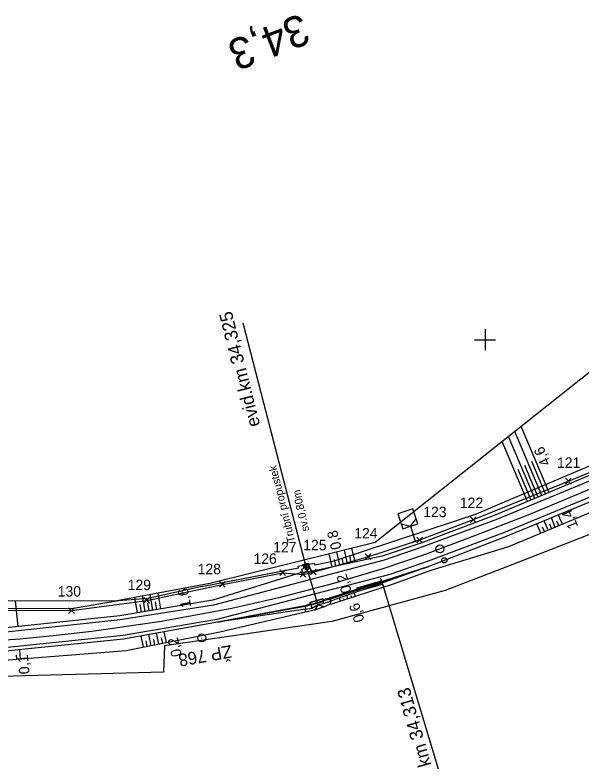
# Model space of a CAD drawing. Extents: x -805730 to -804640, y -1150889 to -1150366.
# Drawn here: x -805190.1 to -805081.4, y -1150682.3 to -1150537.8 of the extents above; entities that cross this region are included whole.
import ezdxf

# ---------------------------------------------------------------- set-up
doc = ezdxf.new("R2010")
doc.units = 0
for name, color, linetype in [('0381KM032-037P - Vrstva 1', 7, 'Continuous'), ('0381KM032-037P - Vrstva 13', 7, 'Continuous'), ('0381KM032-037P - Vrstva 17', 7, 'Continuous'), ('0381KM032-037P - Vrstva 19', 7, 'Continuous'), ('0381KM032-037P - Vrstva 4', 7, 'Continuous'), ('0381KM032-037P - Vrstva 48', 7, 'Continuous'), ('0381KM032-037P - Vrstva 49', 7, 'Continuous'), ('0381KM032-037P - Vrstva 7', 7, 'Continuous'), ('0381KM032-037P - Vrstva 9', 7, 'Continuous'), ('Default', 7, 'Continuous'), ('hran DP - hran DP', 7, 'Continuous'), ('krizky_1000 - Vrstva 1', 7, 'Continuous'), ('PSR_C2_2_Lomove_body_Vimperk - Vrstva 60', 7, 'Continuous'), ('PSR_C2_2_trasa_Vimperk - Kabelová trasa', 7, 'Continuous'), ('vyt_sit - stávající', 7, 'Continuous')]:
    doc.layers.add(name, color=color, linetype=linetype)

msp = doc.modelspace()

# ---------------------------------------------------------------- linework, layer by layer
at = {"layer": '0381KM032-037P - Vrstva 1'}
for points in [[(-805074.24, -1150626.27), (-805091.51, -1150633.48)], [(-805091.51, -1150633.48), (-805101.49, -1150637.38), (-805111.46, -1150641.17)], [(-805111.46, -1150641.17), (-805119.63, -1150643.91), (-805129.05, -1150646.75), (-805139.28, -1150649.43), (-805148.59, -1150651.52), (-805162.04, -1150654.03), (-805175.42, -1150655.94), (-805182.79, -1150656.72)], [(-805182.79, -1150656.72), (-805189.2, -1150657.4), (-805199.42, -1150658.12), (-805222.35, -1150659), (-805235.71, -1150659.34), (-805248.65, -1150659.92), (-805262.34, -1150660.99)]]:
    msp.add_lwpolyline(points, dxfattribs=at)
at = {"layer": '0381KM032-037P - Vrstva 13'}
for p, q in [((-805129.78, -1150649.7), (-805129.65, -1150650.12)), ((-805133.42, -1150650.74), (-805132.59, -1150650.52)), ((-805133.42, -1150650.74), (-805133.23, -1150651.44)), ((-805131.99, -1150650.77), (-805132.69, -1150651.85)), ((-805131.99, -1150650.77), (-805132.2, -1150650.41)), ((-805131.99, -1150650.77), (-805130.88, -1150651.21)), ((-805131, -1150650.07), (-805131.81, -1150650.3)), ((-805130.99, -1150650.58), (-805131, -1150650.07))]:
    msp.add_line(p, q, dxfattribs=at)
for points in [[(-805129.89, -1150649.51), (-805129.78, -1150649.7), (-805131, -1150650.07), (-805131, -1150650.07), (-805131.07, -1150649.74), (-805129.89, -1150649.51)], [(-805134.49, -1150651.14), (-805134.56, -1150650.98), (-805133.46, -1150650.58), (-805133.42, -1150650.74), (-805133.42, -1150650.74), (-805134.49, -1150651.14), (-805134.45, -1150651.61)], [(-805129.65, -1150650.12), (-805129.71, -1150650.67), (-805130.88, -1150651.21), (-805132.69, -1150651.85), (-805134.43, -1150652.2), (-805134.45, -1150651.61), (-805133.23, -1150651.44)], [(-805133.23, -1150651.44), (-805131.99, -1150650.77), (-805130.99, -1150650.58)], [(-805130.99, -1150650.58), (-805129.65, -1150650.12)]]:
    msp.add_lwpolyline(points, dxfattribs=at)
msp.add_ellipse((-805132.2, -1150650.41), major_axis=(-0.388, -0.106), ratio=0.004829, start_param=3.14712, end_param=6.275171, dxfattribs=at)
at = {"layer": '0381KM032-037P - Vrstva 17'}
msp.add_lwpolyline([(-805070.8, -1150598.9), (-805121.06, -1150638.84), (-805152.76, -1150646.7), (-805170.92, -1150650.08), (-805194.39, -1150650.05), (-805213.2, -1150651.26), (-805221.79, -1150652.33), (-805228.79, -1150654.03)], dxfattribs=at)
at = {"layer": '0381KM032-037P - Vrstva 19'}
for p, q in [((-805146.46, -1150596.75), (-805134.12, -1150644.47)), ((-805133.42, -1150650.74), (-805132.59, -1150650.52)), ((-805133.42, -1150650.74), (-805133.42, -1150650.74)), ((-805133.38, -1150650.83), (-805130.98, -1150650.17)), ((-805133.38, -1150650.83), (-805130.98, -1150650.17)), ((-805131.81, -1150650.3), (-805131, -1150650.07))]:
    msp.add_line(p, q, dxfattribs=at)
for points in [[(-805134.98, -1150644.55), (-805135.16, -1150643.96), (-805134.72, -1150643.76), (-805134.94, -1150643.05), (-805134.71, -1150643.05), (-805134.48, -1150643.83)], [(-805134.98, -1150644.55), (-805133.26, -1150644.39), (-805133.87, -1150642.97), (-805134.1, -1150642.94), (-805133.82, -1150643.72)], [(-805134.1, -1150642.94), (-805134.37, -1150642.96), (-805134.71, -1150643.05)], [(-805134.37, -1150642.96), (-805134.35, -1150643.15), (-805134.27, -1150643.62), (-805132.2, -1150650.41)], [(-805133.52, -1150650.35), (-805133.38, -1150650.83), (-805133.38, -1150650.83), (-805133.42, -1150650.74), (-805131, -1150650.07), (-805130.98, -1150650.17), (-805130.98, -1150650.17), (-805131.11, -1150649.68), (-805133.52, -1150650.35)], [(-805131.11, -1150649.68), (-805131.11, -1150649.68), (-805131.07, -1150649.74), (-805131, -1150650.07), (-805131, -1150650.07)], [(-805133.52, -1150650.35), (-805133.52, -1150650.35), (-805133.46, -1150650.58), (-805133.42, -1150650.74)]]:
    msp.add_lwpolyline(points, dxfattribs=at)
for centre, major_axis, ratio, start_param, end_param in [((-805134.15, -1150643.86), (0.331, 0.133), 0.755735, 2.535553, 6.304808), ((-805134.15, -1150643.86), (0.331, 0.133), 0.755735, 0.021623, 2.535553), ((-805132.2, -1150650.41), (0.388, 0.106), 0.004829, 1.569477, 6.288713), ((-805132.2, -1150650.41), (-0.388, -0.106), 0.004829, 3.14712, 4.71107)]:
    msp.add_ellipse(centre, major_axis=major_axis, ratio=ratio, start_param=start_param, end_param=end_param, dxfattribs=at)
at = {"layer": '0381KM032-037P - Vrstva 4'}
for points in [[(-804872.17, -1150539.66), (-804893.72, -1150547.52), (-804911.96, -1150555), (-804952.93, -1150572.63), (-804995.29, -1150590.69), (-805039.86, -1150609.18), (-805057.83, -1150616.69), (-805068.36, -1150621.07), (-805097.92, -1150633.57)], [(-804864.42, -1150538.53), (-804893.06, -1150548.77), (-804911.6, -1150556.2), (-804952.82, -1150573.68), (-804994.86, -1150591.44), (-805039.39, -1150610.13), (-805056.71, -1150617.44), (-805097.6, -1150634.39)], [(-804862.73, -1150542.41), (-804863.39, -1150541.46), (-804892.29, -1150551.48), (-804910.22, -1150558.86), (-804951.61, -1150576.23), (-804993.7, -1150593.96), (-805038.63, -1150612.92), (-805049.62, -1150617.53), (-805055.59, -1150619.94), (-805066.74, -1150624.75), (-805096.44, -1150637.01)], [(-804864.94, -1150543.15), (-804869.59, -1150544.8), (-804891.93, -1150552.26), (-804909.8, -1150559.87), (-804951.24, -1150577.2), (-804993.38, -1150594.6), (-805038.39, -1150613.8), (-805059.54, -1150622.79), (-805066.49, -1150625.57), (-805096.25, -1150637.87)], [(-805097.92, -1150633.57), (-805112.32, -1150638.96), (-805119.74, -1150641.46), (-805133.26, -1150644.39)], [(-805097.6, -1150634.39), (-805112.1, -1150639.75), (-805119.36, -1150642.27), (-805152.08, -1150650.89), (-805169.94, -1150653.7), (-805193.71, -1150656.24), (-805212.28, -1150657.22)], [(-805096.44, -1150637.01), (-805110.9, -1150642.46), (-805118.26, -1150644.98), (-805151.42, -1150653.61), (-805169.41, -1150656.67), (-805193.4, -1150659.17), (-805212.01, -1150660.08)], [(-805096.25, -1150637.87), (-805110.77, -1150643.45), (-805117.97, -1150645.76), (-805129.89, -1150649.51)], [(-805134.98, -1150644.55), (-805152.23, -1150649.93), (-805170.06, -1150652.94), (-805193.76, -1150655.4), (-805212.2, -1150656.84), (-805228.99, -1150656.61)], [(-805134.56, -1150650.98), (-805151.31, -1150654.12), (-805169.36, -1150657.36), (-805193.31, -1150659.84), (-805211.96, -1150660.88), (-805220.23, -1150661.07)]]:
    msp.add_lwpolyline(points, dxfattribs=at)
at = {"layer": '0381KM032-037P - Vrstva 48'}
for p, q in [((-805089.11, -1150629.85), (-805094.3, -1150617.57)), ((-805087.73, -1150629.26), (-805093.08, -1150616.6)), ((-805090.49, -1150630.43), (-805095.52, -1150618.54)), ((-805091.87, -1150631.02), (-805096.74, -1150619.51)), ((-805088.42, -1150629.55), (-805091.05, -1150623.32)), ((-805091.18, -1150630.72), (-805093.66, -1150624.87)), ((-805089.8, -1150630.14), (-805092.35, -1150624.1)), ((-805085.16, -1150635.34), (-805085.89, -1150633.59)), ((-805087.93, -1150636.49), (-805088.67, -1150634.73)), ((-805086.55, -1150635.91), (-805087.28, -1150634.16)), ((-805085.85, -1150635.62), (-805086.22, -1150634.75)), ((-805089.32, -1150637.07), (-805090.05, -1150635.3)), ((-805088.62, -1150636.78), (-805088.99, -1150635.9)), ((-805087.24, -1150636.2), (-805087.61, -1150635.32)), ((-805129.34, -1150643.54), (-805129.89, -1150641.03)), ((-805127.87, -1150643.22), (-805128.43, -1150640.67)), ((-805126.41, -1150642.91), (-805126.97, -1150640.3)), ((-805124.94, -1150642.59), (-805125.52, -1150639.94)), ((-805128.61, -1150643.38), (-805128.88, -1150642.11)), ((-805127.14, -1150643.06), (-805127.42, -1150641.78)), ((-805125.68, -1150642.75), (-805125.96, -1150641.44)), ((-805125.89, -1150648.25), (-805125.84, -1150648.39)), ((-805166.64, -1150652.36), (-805167.14, -1150649.38)), ((-805165.16, -1150652.11), (-805165.66, -1150649.1)), ((-805163.68, -1150651.86), (-805164.19, -1150648.83)), ((-805162.2, -1150651.61), (-805162.71, -1150648.55)), ((-805128.75, -1150649.15), (-805128.69, -1150649.34)), ((-805128.03, -1150648.93), (-805128.01, -1150649.01)), ((-805127.72, -1150650.11), (-805127.92, -1150649.5)), ((-805127.32, -1150648.7), (-805127.27, -1150648.86)), ((-805127.01, -1150649.88), (-805127.11, -1150649.57)), ((-805126.6, -1150648.48), (-805126.58, -1150648.55)), ((-805126.29, -1150649.66), (-805126.5, -1150649)), ((-805125.58, -1150649.43), (-805125.69, -1150649.09)), ((-805124.86, -1150649.2), (-805125.09, -1150648.51)), ((-805189.5, -1150654.96), (-805190.01, -1150650.05)), ((-805165.9, -1150652.24), (-805166.15, -1150650.74)), ((-805164.42, -1150651.99), (-805164.67, -1150650.48)), ((-805162.94, -1150651.74), (-805163.19, -1150650.22)), ((-805165.5, -1150658.95), (-805165.94, -1150656.75)), ((-805164.03, -1150658.66), (-805164.46, -1150656.48)), ((-805162.56, -1150658.36), (-805162.99, -1150656.22)), ((-805161.09, -1150658.07), (-805161.51, -1150655.95)), ((-805164.77, -1150658.8), (-805164.98, -1150657.71)), ((-805163.3, -1150658.51), (-805163.51, -1150657.43)), ((-805161.82, -1150658.22), (-805162.04, -1150657.15)), ((-805189.06, -1150661.23), (-805189.2, -1150659.41)), ((-805189.8, -1150661.29), (-805189.88, -1150660.39))]:
    msp.add_line(p, q, dxfattribs=at)
at = {"layer": '0381KM032-037P - Vrstva 49'}
for p, q in [((-805134.98, -1150644.55), (-805133.26, -1150644.39)), ((-805129.78, -1150649.7), (-805117.97, -1150645.76)), ((-805134.49, -1150651.14), (-805151.31, -1150654.12)), ((-805134.45, -1150651.61), (-805151.31, -1150654.12))]:
    msp.add_line(p, q, dxfattribs=at)
for points in [[(-804871.36, -1150538.86), (-804872.17, -1150539.66), (-804893.72, -1150547.52), (-804911.96, -1150555), (-804952.93, -1150572.63), (-804995.29, -1150590.69), (-805039.86, -1150609.18), (-805057.83, -1150616.69), (-805068.36, -1150621.07), (-805097.92, -1150633.57)], [(-804909.8, -1150559.87), (-804951.24, -1150577.2), (-804993.38, -1150594.6), (-805038.39, -1150613.8), (-805050.01, -1150619.25), (-805055.21, -1150621.51), (-805059.54, -1150622.79), (-805066.49, -1150625.57), (-805096.25, -1150637.87)], [(-805070.8, -1150598.9), (-805121.06, -1150638.84), (-805152.76, -1150646.7), (-805170.92, -1150650.08), (-805194.39, -1150650.05), (-805213.2, -1150651.26), (-805221.79, -1150652.33), (-805228.79, -1150654.03)], [(-805065.73, -1150627.22), (-805095.53, -1150639.67)], [(-805097.92, -1150633.57), (-805112.32, -1150638.96), (-805119.74, -1150641.46), (-805133.26, -1150644.39)], [(-805096.25, -1150637.87), (-805110.77, -1150643.45), (-805129.65, -1150650.12)], [(-805095.53, -1150639.67), (-805110.42, -1150644.21), (-805117.6, -1150646.87), (-805129.42, -1150650.66)], [(-805129.89, -1150649.51), (-805117.97, -1150645.76), (-805110.77, -1150643.45)], [(-805134.98, -1150644.55), (-805152.23, -1150649.93), (-805170.06, -1150652.94), (-805193.76, -1150655.4), (-805212.2, -1150656.84), (-805221.82, -1150655.55)], [(-805151.31, -1150654.12), (-805134.56, -1150650.98), (-805133.46, -1150650.58), (-805133.52, -1150650.35), (-805133.52, -1150650.35), (-805131.11, -1150649.68), (-805131.11, -1150649.68), (-805131.07, -1150649.74), (-805129.89, -1150649.51)], [(-805129.78, -1150649.7), (-805131, -1150650.07), (-805131.81, -1150650.3)], [(-805134.49, -1150651.14), (-805133.42, -1150650.74), (-805132.59, -1150650.52)], [(-805134.45, -1150651.61), (-805133.23, -1150651.44), (-805131.99, -1150650.77), (-805130.99, -1150650.58), (-805129.65, -1150650.12)], [(-805129.42, -1150650.66), (-805129.71, -1150650.67), (-805130.88, -1150651.21), (-805132.69, -1150651.85), (-805134.43, -1150652.2)], [(-805134.43, -1150652.2), (-805150.83, -1150656.03), (-805168.82, -1150659.61), (-805193.05, -1150661.55), (-805211.83, -1150662.42), (-805220.04, -1150663.05)], [(-805151.31, -1150654.12), (-805169.36, -1150657.36), (-805193.31, -1150659.84), (-805211.96, -1150660.88), (-805220.13, -1150661.62)]]:
    msp.add_lwpolyline(points, dxfattribs=at)
msp.add_ellipse((-805132.2, -1150650.41), major_axis=(0.388, 0.106), ratio=0.004829, start_param=0.005528, end_param=3.133579, dxfattribs=at)
at = {"layer": '0381KM032-037P - Vrstva 7'}
for p, q in [((-805114.33, -1150635.74), (-805113.38, -1150638.58)), ((-805113.85, -1150638.74), (-805112.9, -1150638.42)), ((-805107.87, -1150642.28), (-805107.77, -1150642.28))]:
    msp.add_line(p, q, dxfattribs=at)
for points in [[(-805114.33, -1150635.74), (-805112.91, -1150635.26), (-805113.86, -1150632.42), (-805116.71, -1150633.37), (-805115.75, -1150636.22), (-805114.33, -1150635.74)], [(-805116.07, -1150635.27), (-805114.33, -1150635.74), (-805113.23, -1150634.31)]]:
    msp.add_lwpolyline(points, dxfattribs=at)
for centre, radius in [((-805108.67, -1150640.09), 0.75), ((-805107.82, -1150642.28), 0.5)]:
    msp.add_circle(centre, radius, dxfattribs=at)
at = {"layer": '0381KM032-037P - Vrstva 9'}
for p, q in [((-805119.84, -1150646.28), (-805124.65, -1150647.63)), ((-805119.84, -1150646.28), (-805120, -1150645.7)), ((-805119.68, -1150646.86), (-805119.84, -1150646.28)), ((-805119.76, -1150646.57), (-805109, -1150682.26)), ((-805124.65, -1150647.63), (-805124.49, -1150648.21)), ((-805124.49, -1150648.21), (-805119.68, -1150646.86))]:
    msp.add_line(p, q, dxfattribs=at)
at = {"layer": 'hran DP - hran DP'}
for p, q in [((-805096.7, -1150631.27), (-805066.7, -1150618.51)), ((-805101.66, -1150633.38), (-805096.7, -1150631.27)), ((-805105.89, -1150634.79), (-805101.66, -1150633.38)), ((-805128.92, -1150642.38), (-805105.89, -1150634.79)), ((-805077.33, -1150636.32), (-805095.21, -1150643.26)), ((-805132.67, -1150643.17), (-805128.92, -1150642.38)), ((-805153.67, -1150647.14), (-805135.75, -1150643.74)), ((-805135.82, -1150643.41), (-805132.75, -1150642.8)), ((-805135.75, -1150643.74), (-805135.82, -1150643.41)), ((-805132.75, -1150642.8), (-805132.67, -1150643.17)), ((-805095.21, -1150643.26), (-805102.65, -1150646.15)), ((-805102.65, -1150646.15), (-805107.63, -1150648.08)), ((-805164.69, -1150649.54), (-805154.57, -1150647.29)), ((-805154.57, -1150647.29), (-805153.67, -1150647.14)), ((-805107.63, -1150648.08), (-805129.38, -1150653.98)), ((-805170.32, -1150649.99), (-805164.69, -1150649.54)), ((-805178.93, -1150651.45), (-805170.32, -1150649.99)), ((-805208.17, -1150651.53), (-805178.93, -1150651.45)), ((-805129.38, -1150653.98), (-805161.49, -1150658.69)), ((-805161.49, -1150658.69), (-805161.69, -1150663.73)), ((-805161.69, -1150663.73), (-805193.03, -1150664.54))]:
    msp.add_line(p, q, dxfattribs=at)
at = {"layer": 'krizky_1000 - Vrstva 1'}
for points in [[(-805100, -1150598), (-805100, -1150602)], [(-805102, -1150600), (-805098, -1150600)]]:
    msp.add_lwpolyline(points, dxfattribs=at)
at = {"layer": 'PSR_C2_2_Lomove_body_Vimperk - Vrstva 60'}
for p, q in [((-805084.58, -1150627.66), (-805083.48, -1150626.56)), ((-805083.48, -1150627.66), (-805084.58, -1150626.56)), ((-805102.8, -1150635.01), (-805101.7, -1150633.91)), ((-805101.7, -1150635.01), (-805102.8, -1150633.91)), ((-805113.08, -1150638.92), (-805111.98, -1150637.82)), ((-805111.98, -1150638.92), (-805113.08, -1150637.82)), ((-805123, -1150642.14), (-805121.9, -1150641.04)), ((-805121.9, -1150642.14), (-805123, -1150641.04)), ((-805139.34, -1150645.21), (-805138.24, -1150644.11)), ((-805138.24, -1150645.21), (-805139.34, -1150644.11)), ((-805135.45, -1150645.52), (-805134.35, -1150644.42)), ((-805134.35, -1150645.52), (-805135.45, -1150644.42)), ((-805133.5, -1150645.08), (-805132.4, -1150643.98)), ((-805132.4, -1150645.08), (-805133.5, -1150643.98)), ((-805150.91, -1150647.45), (-805149.81, -1150646.35)), ((-805149.81, -1150647.45), (-805150.91, -1150646.35)), ((-805165.43, -1150650.5), (-805164.33, -1150649.4)), ((-805164.33, -1150650.5), (-805165.43, -1150649.4)), ((-805179.86, -1150652.46), (-805178.76, -1150651.36)), ((-805178.76, -1150652.46), (-805179.86, -1150651.36))]:
    msp.add_line(p, q, dxfattribs=at)
at = {"layer": 'PSR_C2_2_trasa_Vimperk - Kabelová trasa'}
for points in [[(-805122.45, -1150641.59), (-805112.53, -1150638.37), (-805102.25, -1150634.46), (-805084.03, -1150627.11), (-805075.4, -1150623.5), (-805060.17, -1150617.08), (-805047.9, -1150611.92), (-805039.79, -1150608.5), (-804989.01, -1150587.76)], [(-805214.1, -1150652.28), (-805208.19, -1150651.74), (-805179.31, -1150651.91), (-805164.88, -1150649.95), (-805150.36, -1150646.9), (-805138.79, -1150644.66), (-805134.9, -1150644.97), (-805132.95, -1150644.53), (-805122.45, -1150641.59)]]:
    msp.add_lwpolyline(points, dxfattribs=at)
at = {"layer": 'vyt_sit - stávající'}
msp.add_line((-805154.38, -1150657.15), (-805154.28, -1150657.15), dxfattribs=at)
msp.add_circle((-805154.33, -1150657.15), 0.756, dxfattribs=at)

# ---------------------------------------------------------------- texts
at = {"layer": '0381KM032-037P - Vrstva 19'}
for s, height, rotation, p in [('evid.km 34,325', 2.5, 104.0597, (-805143.1, -1150616.37)), ('Trubní propustek', 1.5, 104.0315, (-805136.39, -1150638.68)), ('sv.0,80m', 1.5, 102.6099, (-805133.72, -1150636.58))]:
    msp.add_text(s, height=height, rotation=rotation, dxfattribs=at).set_placement(p)
at = {"layer": '0381KM032-037P - Vrstva 48'}
for s, rotation, p in [('4,6', 113.4709, (-805087.41, -1150623.69)), ('1,4', 112.4607, (-805082.11, -1150635.78)), ('0,8', 103.9362, (-805127.51, -1150639.96)), ('0,2', 106.8529, (-805125.55, -1150648.25)), ('1,6', 100.857, (-805156.33, -1150651.13)), ('0,6', 107.7953, (-805123.1, -1150653.81)), ('0,2', 103.235, (-805158.12, -1150660.52)), ('0,1', 95.8989, (-805187.31, -1150664))]:
    msp.add_text(s, height=2, rotation=rotation, dxfattribs=at).set_placement(p)
at = {"layer": '0381KM032-037P - Vrstva 7'}
msp.add_text('34,3', height=6, rotation=201.0798, dxfattribs=at).set_placement((-805135.2, -1150537.34))
at = {"layer": '0381KM032-037P - Vrstva 9'}
msp.add_text('km 34,313', height=2.5, rotation=105.6206, dxfattribs=at).set_placement((-805110.3, -1150681.5))
at = {"layer": 'Default'}
for s, p in [('121', (-805086.2, -1150624.56)), ('122', (-805104.83, -1150632.25)), ('123', (-805111.85, -1150634)), ('124', (-805125.08, -1150638.08)), ('127', (-805140.62, -1150640.76)), ('125', (-805134.86, -1150640.35)), ('126', (-805144.41, -1150642.96)), ('128', (-805155.11, -1150644.94)), ('129', (-805168.53, -1150647.99)), ('130', (-805181.94, -1150649.22))]:
    msp.add_text(s, height=2, dxfattribs=at).set_placement(p)
at = {"layer": 'vyt_sit - stávající'}
msp.add_text('ŽP 768', height=2.4, rotation=190, dxfattribs=at).set_placement((-805148.77, -1150658.51))

doc.saveas('drawing.dxf')
